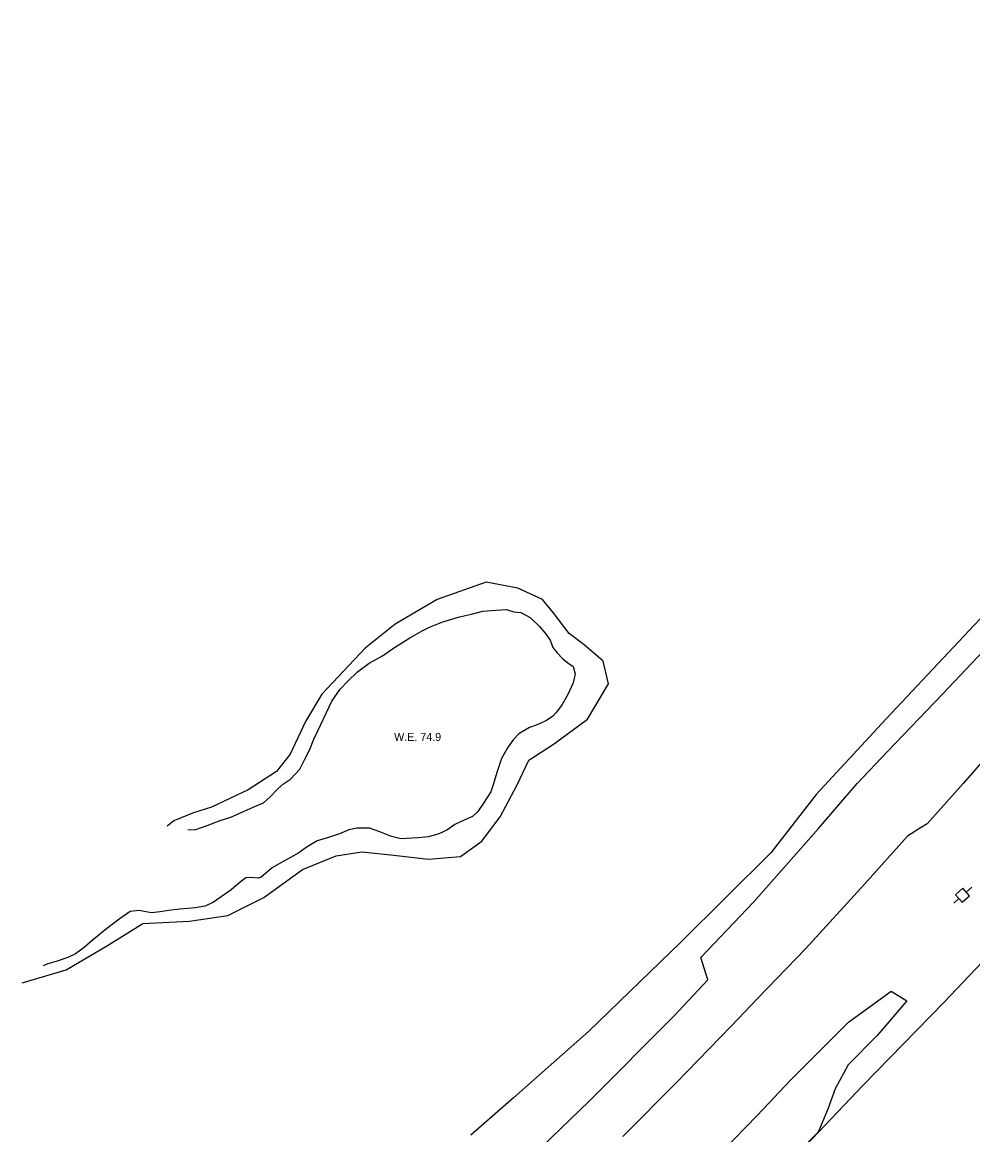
# Model space of a CAD drawing. Extents: x 2161152 to 2175754, y 602179 to 617749.
# Drawn here: x 2172161 to 2172636, y 614246 to 614802 of the extents above; entities that cross this region are included whole.
import ezdxf

# ---------------------------------------------------------------- set-up
doc = ezdxf.new("R2010")
doc.units = 0
for name, color, linetype in [('RD_EX_Fence_ChLk', 7, 'Continuous'), ('RD_EX_H2O', 7, 'Continuous'), ('RD_EX_H2O_txCode', 7, 'Continuous'), ('RD_EX_Road', 7, 'Continuous'), ('RD_EX_UT', 7, 'Continuous'), ('RD_EX_VEG', 7, 'Continuous')]:
    doc.layers.add(name, color=color, linetype=linetype)

msp = doc.modelspace()

# ---------------------------------------------------------------- linework, layer by layer
at = {"layer": 'RD_EX_Fence_ChLk'}
msp.add_lwpolyline([(2173205.02, 614957.05), (2173199.88, 614924.75), (2173136.55, 614854.57), (2173088.24, 614801.53), (2172940.56, 614645.2), (2172865.47, 614567.1), (2172818.3, 614518.44), (2172766.82, 614464.29), (2172685.57, 614379.6), (2172621.61, 614312.29), (2172581.2, 614270.87), (2172439.13, 614121.36), (2172363.9, 614045.23), (2172327.58, 614008.26), (2172265.65, 613941.63), (2172203.37, 613870.32)], dxfattribs=at)
at = {"layer": 'RD_EX_H2O'}
msp.add_lwpolyline([(2172243.92, 614398.54), (2172248.03, 614398.74), (2172253.58, 614400.71), (2172260.19, 614403.32), (2172265.53, 614404.83), (2172272.15, 614407.84), (2172276.63, 614409.82), (2172281.84, 614411.99), (2172285.08, 614415.12), (2172288.93, 614418.98), (2172291.76, 614421.59), (2172295.25, 614423.92), (2172299.97, 614428.88), (2172302.38, 614433.82), (2172304.71, 614438.43), (2172306.92, 614443.83), (2172310.63, 614451.47), (2172315.87, 614462.93), (2172320.14, 614468.9), (2172323.86, 614472.89), (2172328.78, 614477.52), (2172334.56, 614481.8), (2172341.19, 614485.47), (2172346.29, 614488.97), (2172349.97, 614491.36), (2172354.94, 614494.47), (2172361.43, 614498.14), (2172364.64, 614499.81), (2172371.32, 614502.49), (2172379.72, 614505), (2172385.78, 614506.3), (2172391.38, 614507.8), (2172397.89, 614508.35), (2172403.13, 614508.6), (2172406.83, 614507.48), (2172410.34, 614507.22), (2172415.07, 614504.62), (2172419.71, 614500.23), (2172422.57, 614496.87), (2172425.03, 614493.38), (2172426.3, 614489.64), (2172428.51, 614486.95), (2172431.11, 614484.12), (2172433.8, 614482.02), (2172436.55, 614480.12), (2172437.56, 614476.52), (2172436.42, 614472.03), (2172433.87, 614466.17), (2172430.93, 614461.11), (2172428.22, 614457.44), (2172426.13, 614455.28), (2172422.9, 614452.95), (2172418.56, 614450.96), (2172414.62, 614449.77), (2172409.4, 614446.54), (2172406.69, 614443.66), (2172403.98, 614439.99), (2172400.76, 614434.14), (2172398.39, 614427.28), (2172396.5, 614421), (2172395.32, 614417.64), (2172391.77, 614411.86), (2172388.78, 614407.66), (2172386.22, 614405.31), (2172382.34, 614403.65), (2172377.33, 614401.28), (2172373.37, 614398.49), (2172369.35, 614396.57), (2172364.22, 614395.12), (2172358.83, 614394.62), (2172350.46, 614394.09), (2172345.77, 614395.3), (2172339.84, 614397.65), (2172334.69, 614399.46), (2172328.65, 614399.36), (2172324.39, 614398.5), (2172319.71, 614396.59), (2172314.24, 614394.69), (2172308.63, 614393.05), (2172303.67, 614390.08), (2172299.37, 614387.1), (2172295.29, 614384.84), (2172290.46, 614382.13), (2172286.04, 614379.55), (2172280.65, 614374.99), (2172279.18, 614374.35), (2172275.61, 614374.81), (2172273.01, 614374.52), (2172269.38, 614371.79), (2172265.61, 614368.67), (2172262.25, 614366.2), (2172256.81, 614362.37), (2172252.73, 614360.38), (2172247.67, 614359.54), (2172240.02, 614358.93), (2172234.44, 614358.23), (2172230.18, 614357.64), (2172225.79, 614357.18), (2172222.14, 614357.7), (2172219.7, 614358.34), (2172215.17, 614357.75), (2172209.73, 614353.92), (2172203.35, 614349.18), (2172196.28, 614343.25), (2172192.17, 614339.8), (2172187.93, 614336.62), (2172183.98, 614334.76), (2172178.77, 614332.98), (2172174.04, 614331.67), (2172171.69, 614330.58)], dxfattribs=at)
at = {"layer": 'RD_EX_Road'}
for points in [[(2172397, 614217.2), (2172444.5, 614263.07), (2172486.73, 614305.55), (2172503.83, 614323.56), (2172500.2, 614334.82), (2172526.61, 614362.46), (2172558.97, 614399.21), (2172578.44, 614421.68), (2172593.46, 614437.76), (2172621.06, 614466.28), (2172644.25, 614491.05)], [(2172658.89, 614453.41), (2172631.25, 614421.75), (2172613.28, 614401.51), (2172609.55, 614399.2), (2172603.43, 614395.36), (2172581.97, 614371.48), (2172552.6, 614339.18), (2172528.75, 614314.54), (2172515.34, 614300.57), (2172487.86, 614272.11), (2172461.35, 614245.32)]]:
    msp.add_lwpolyline(points, dxfattribs=at)
at = {"layer": 'RD_EX_UT'}
for p, q in [((2172631.21, 614369.42), (2172627.48, 614366.1)), ((2172634.54, 614365.69), (2172631.21, 614369.42)), ((2172632.86, 614367.46), (2172635.58, 614369.88)), ((2172626.62, 614361.9), (2172629.21, 614364.21)), ((2172627.48, 614366.1), (2172630.8, 614362.36)), ((2172630.8, 614362.36), (2172634.54, 614365.69))]:
    msp.add_line(p, q, dxfattribs=at)
at = {"layer": 'RD_EX_VEG'}
for points in [[(2172747.65, 614806.74), (2172761.18, 614789.82), (2172769.77, 614777.93), (2172777.07, 614771.03), (2172785.69, 614763.34), (2172790.59, 614751.47), (2172778.59, 614730.27), (2172760.76, 614702.26), (2172737.47, 614684.03), (2172730.26, 614670.14), (2172733.56, 614655.64), (2172739.28, 614646.65), (2172744.46, 614635.03), (2172732.47, 614615.93), (2172721.56, 614599.44), (2172674.81, 614540.71), (2172636.76, 614500.78), (2172592.79, 614454.09), (2172557.92, 614416.21), (2172535.3, 614387.06), (2172490.28, 614342.47), (2172444.19, 614297.87), (2172406.71, 614264.72), (2172385.29, 614246.07)], [(2172161.27, 614322.18), (2172183.15, 614328.72), (2172203.79, 614340.86), (2172221.48, 614351.71), (2172244.86, 614352.92), (2172264.01, 614355.79), (2172281.94, 614364.78), (2172301.27, 614378.78), (2172318.09, 614385.67), (2172330.85, 614387.58), (2172345.41, 614386.01), (2172364.2, 614383.85), (2172380.13, 614385.18), (2172390.86, 614392.95), (2172400.08, 614405), (2172408.56, 614421.03), (2172414.33, 614433.4), (2172427.19, 614441.67), (2172443.57, 614453.86), (2172454.19, 614471.44), (2172451.47, 614482.88), (2172442.06, 614490.98), (2172434.47, 614496.67), (2172426.43, 614507.14), (2172421.24, 614513.59), (2172408.87, 614519.36), (2172393.02, 614522.27), (2172368.49, 614513.66), (2172347.6, 614501.28), (2172332.55, 614489.32), (2172310.94, 614466.33), (2172302.75, 614452.67), (2172295.05, 614436.34), (2172288.28, 614427.7), (2172274.07, 614418.64), (2172255.88, 614409.92), (2172246.28, 614406.9), (2172236.92, 614403.07), (2172233.69, 614400.47)], [(2172511.25, 614238.27), (2172528.4, 614255.9), (2172545.03, 614273.55), (2172559.49, 614288.06), (2172573.95, 614302.57), (2172595.28, 614318.02), (2172603.1, 614313.15), (2172588.32, 614295.75), (2172573.86, 614281.23), (2172567.33, 614269.22), (2172563.74, 614259), (2172558.8, 614247.47), (2172544.31, 614232.94)]]:
    msp.add_lwpolyline(points, dxfattribs=at)

# ---------------------------------------------------------------- texts
at = {"layer": 'RD_EX_H2O_txCode'}
msp.add_text('W.E. 74.9', height=4, dxfattribs=at).set_placement((2172347.05, 614443))

doc.saveas('drawing.dxf')
